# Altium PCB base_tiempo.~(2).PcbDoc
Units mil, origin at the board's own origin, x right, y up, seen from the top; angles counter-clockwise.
Board outline 6000 x 4000 mil, 2 copper layers (Top Layer, Bottom Layer); 3 components, 17 nets, 48 pads, 0 vias.
Unrouted connection lines stored in the file: 16.
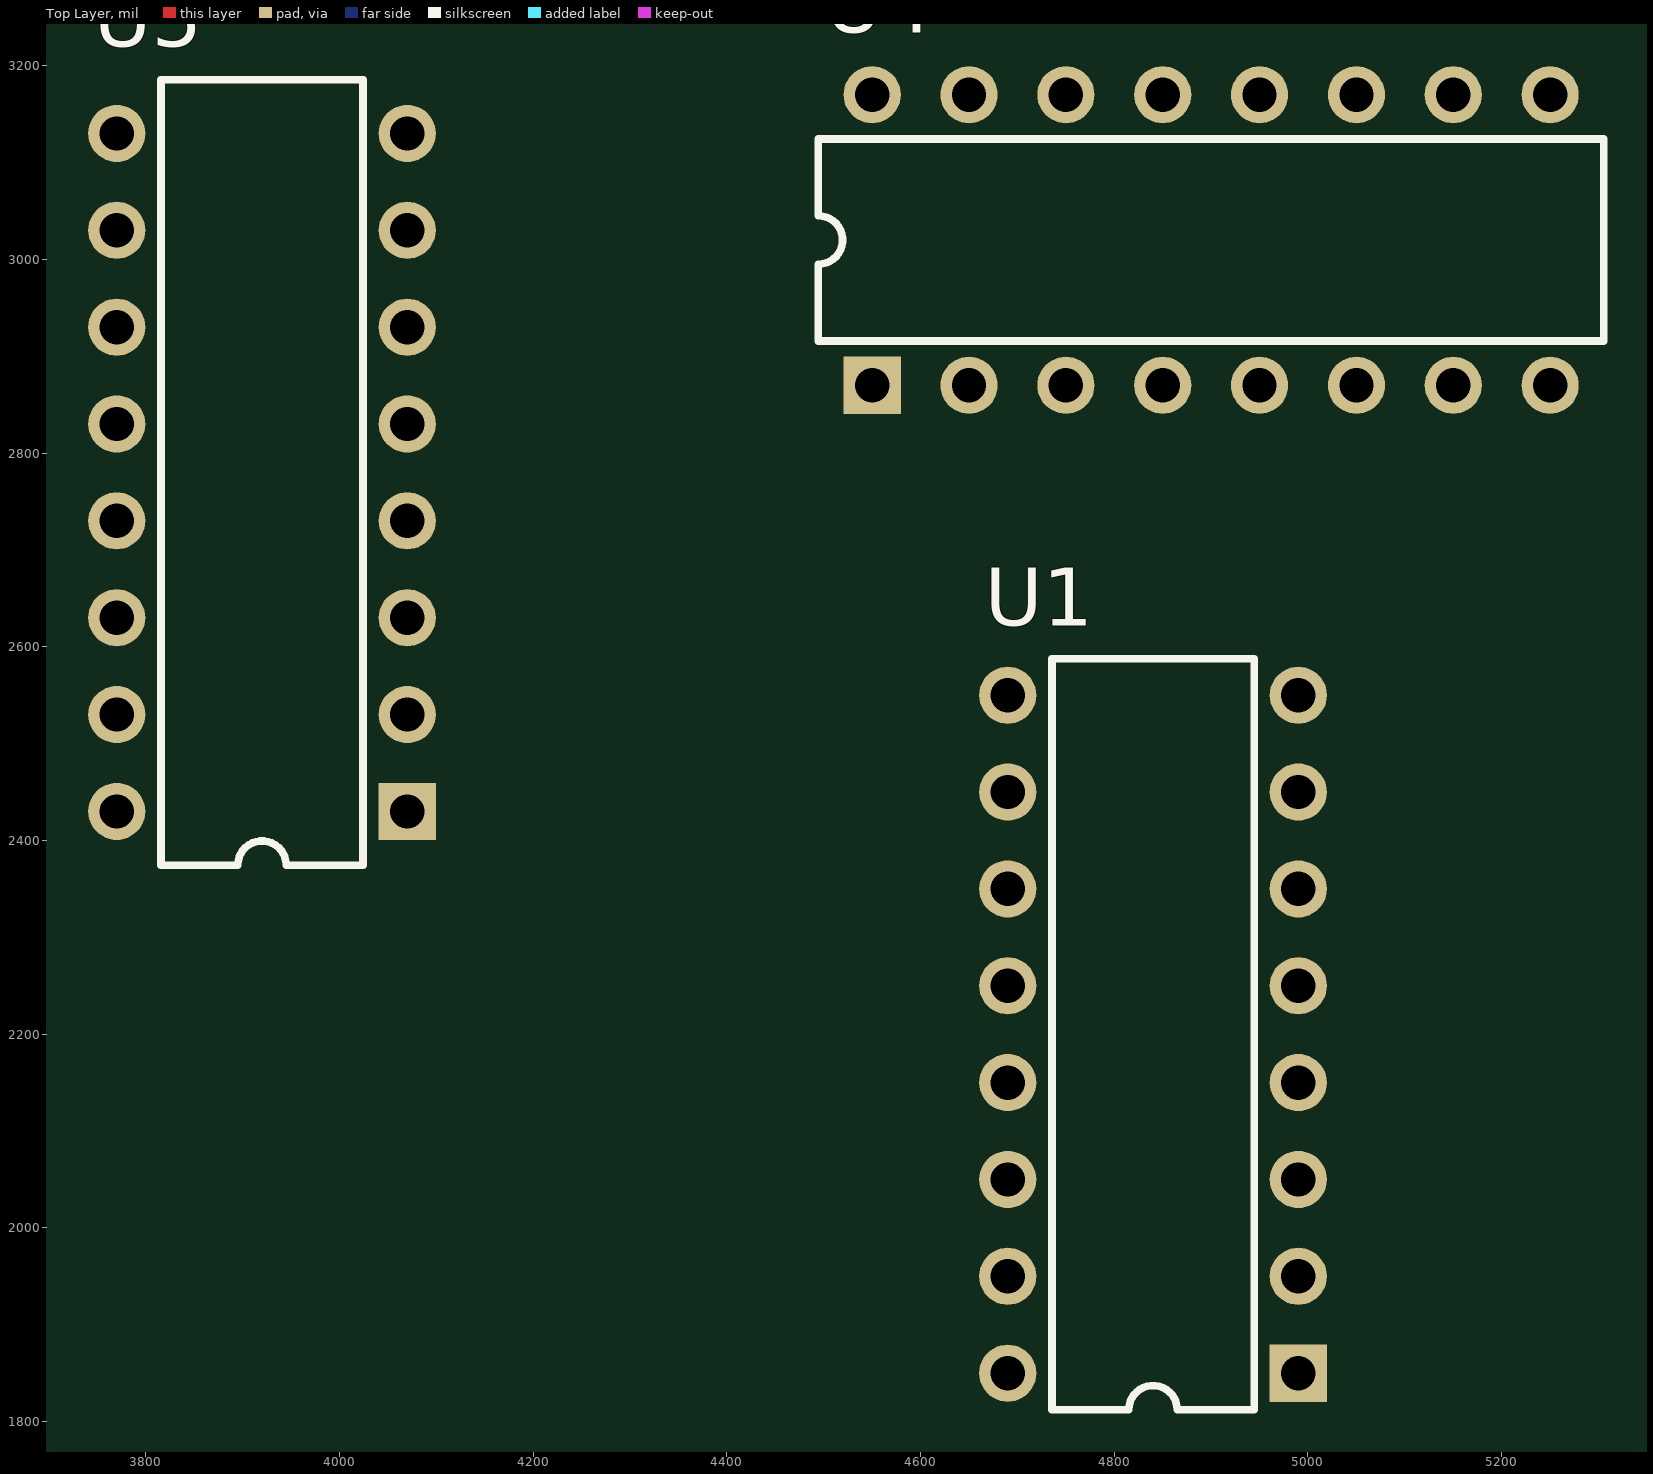
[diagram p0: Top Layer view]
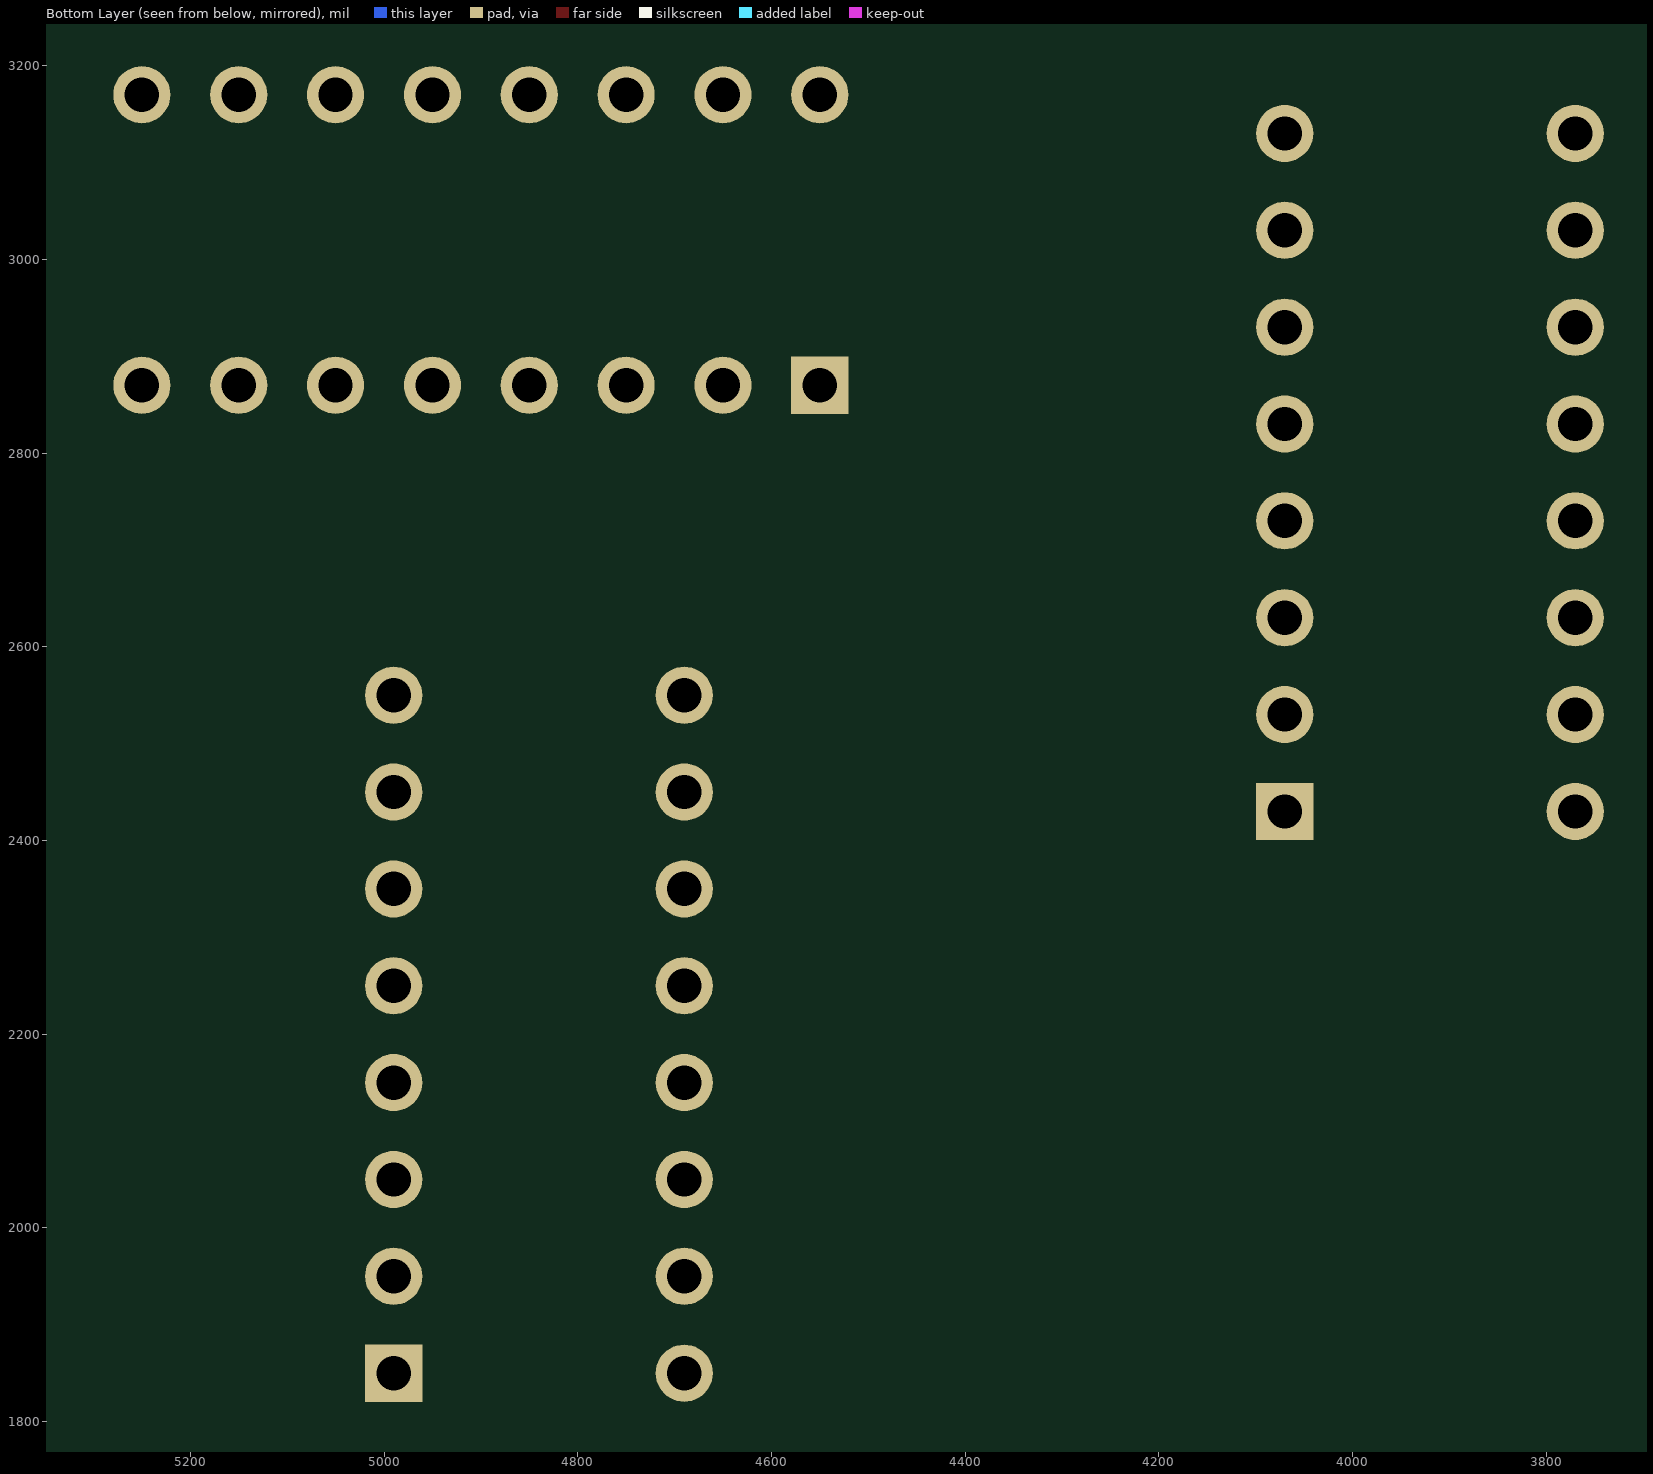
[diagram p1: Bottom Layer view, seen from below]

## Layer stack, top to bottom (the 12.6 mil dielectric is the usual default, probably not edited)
Top Layer: signal copper 1.4
Dielectric: dielectric 12.6, FR-4, Dk 4.8
Bottom Layer: signal copper 1.4

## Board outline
1000,1000 7000,1000 7000,5000 1000,5000

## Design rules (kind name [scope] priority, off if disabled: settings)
Clearance [All] p1: gap=10
PolygonConnect [All] p1: connectstyle=Relief reliefconductorwidth=10 reliefentries=4 polygonreliefangle="90 Angle"
RoomDefinition Designator [InComponentClass('Designator')] p1: confinementstyle=ConfineIn formatcopy=TRUE lockcomponents=FALSE outline 7045,1810 7845,1810 7845,2740 7045,2740
RoomDefinition base_tiempo [InComponentClass('base_tiempo')] p2: confinementstyle=ConfineIn formatcopy=TRUE lockcomponents=FALSE outline 7045,960 7845,960 7845,1860 7045,1860
RoutingVias [All] p1: holewidth=28 width=50 viastyle="Through Hole" minholewidth=28 minwidth=50 maxholewidth=28 maxwidth=50
SilkscreenOverComponentPads [All] p1: minsilkscreentomaskgap=10
SolderMaskExpansion [All] p1: expansion=4
TestPointUsage [All] p1: valid=0 allowmultiple=FALSE
Testpoint [All] p1: side=15 testpointundercomponent=TRUE minsize=40 maxsize=100 preferedsize=60 minholesize=0 maxholesize=40 preferedholesize=32 testpointgrid=1 style=1023 order=0123456789
Width [All] p1: maxlimit=10 minlimit=10 preferedwidth=10
23 further rules are at their usual default settings.

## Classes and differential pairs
component class Designator: U4 U5
component class base_tiempo: U1

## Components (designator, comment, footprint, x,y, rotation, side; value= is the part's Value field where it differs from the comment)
U1 "SN74HC4040N" N016 4840,2200 r90 top
U4 "M54HC4050F1R" DIP16 4900,3020 r0 top
U5 "M54HC4049F1R" DIP16 3920,2780 r90 top

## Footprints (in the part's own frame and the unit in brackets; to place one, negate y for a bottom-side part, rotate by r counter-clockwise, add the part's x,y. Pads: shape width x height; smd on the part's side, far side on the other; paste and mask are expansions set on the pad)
DIP16 [mm] "DIP; 16 Leads; Row Spacing 7.62 mm; Pitch 2.54 mm"
  rect 1.5x1.5 hole 0.9: 1(-8.89,-3.81)
  round 1.5 hole 0.9: 2(-6.35,-3.81) 3(-3.81,-3.81) 4(-1.27,-3.81) 5(1.27,-3.81) 6(3.81,-3.81) 7(6.35,-3.81) 8(8.89,-3.81) 9(8.89,3.81) 10(6.35,3.81) 11(3.81,3.81) 12(1.27,3.81) 13(-1.27,3.81) 14(-3.81,3.81) 15(-6.35,3.81) 16(-8.89,3.81)
  silkscreen extent -10.3,-2.65 10.3,2.65
N016 [mm] "DIP; 16 Leads; Row Spacing 7.62 mm; Pitch 2.54 mm"
  rect 1.5x1.5 hole 0.9: 1(-8.89,-3.81)
  round 1.5 hole 0.9: 2(-6.35,-3.81) 3(-3.81,-3.81) 4(-1.27,-3.81) 5(1.27,-3.81) 6(3.81,-3.81) 7(6.35,-3.81) 8(8.89,-3.81) 9(8.89,3.81) 10(6.35,3.81) 11(3.81,3.81) 12(1.27,3.81) 13(-1.27,3.81) 14(-3.81,3.81) 15(-6.35,3.81) 16(-8.89,3.81)
  silkscreen extent -9.85,-2.65 9.85,2.65

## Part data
U1: "12-Bit Asynchronous Binary Counter"
U4: "Hex Buffer/Converter Non-Inverting"
U5: "Hex Buffer/Converter Invertering"

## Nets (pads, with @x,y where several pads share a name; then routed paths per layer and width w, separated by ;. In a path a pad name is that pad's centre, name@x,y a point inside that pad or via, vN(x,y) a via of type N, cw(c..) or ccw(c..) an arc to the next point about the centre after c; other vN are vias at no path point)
B_0: U1.9 U4.3 U5.3
B_1: U1.7 U4.5 U5.5
B_2: U1.6 U4.7 U5.7
B_3: U1.5 U4.9 U5.9
B_4: U1.3 U4.11 U5.11
GND: U1.8 U4.8 U5.8
NetU4_2: U4.2
NetU4_4: U4.4
NetU4_6: U4.6
NetU4_10: U4.10
NetU4_12: U4.12
NetU5_2: U5.2
NetU5_4: U5.4
NetU5_6: U5.6
NetU5_10: U5.10
NetU5_12: U5.12
VCC: U1.10 U1.11 U1.16 U4.1 U5.1
pads on no net: U1.1 U1.2 U1.4 U1.12 U1.13 U1.14 U1.15 U4.13 U4.14 U4.15 U4.16 U5.13 U5.14 U5.15 U5.16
